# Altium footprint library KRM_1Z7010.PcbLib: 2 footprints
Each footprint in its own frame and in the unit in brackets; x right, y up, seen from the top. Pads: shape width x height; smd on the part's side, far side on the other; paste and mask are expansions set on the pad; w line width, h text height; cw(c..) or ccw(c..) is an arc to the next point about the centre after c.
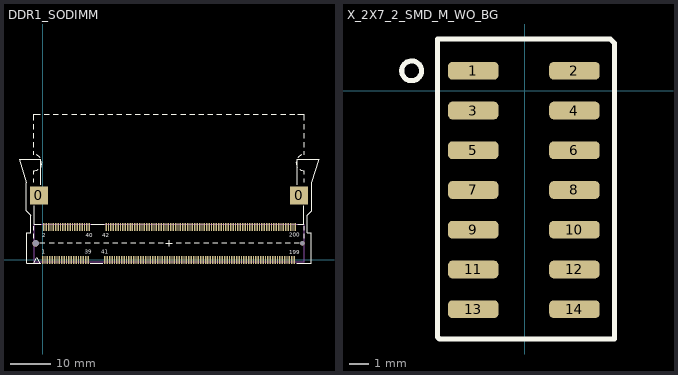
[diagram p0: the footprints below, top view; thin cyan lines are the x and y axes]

## DDR1_SODIMM [mm] "SO DIMM SOCKET DDR STD 2V5"
pads (204):
  round 1.55 hole 1.6 unplated: 0(-1.75,4.1)
  rect 4.5x4.6 smd: 0(-0.9,16.1) 0(64.2,16.1)
  round 1.05 hole 1.1 unplated: 0(65.05,4.1)
  rect 0.35x2 smd: 1(0,0) 2(0.3,8.2) 3(0.6,0) 4(0.9,8.2) 5(1.2,0) 6(1.5,8.2) 7(1.8,0) 8(2.1,8.2) 9(2.4,0) 10(2.7,8.2) 11(3,0) 12(3.3,8.2) 13(3.6,0) 14(3.9,8.2) 15(4.2,0) 16(4.5,8.2) 17(4.8,0) 18(5.1,8.2) 19(5.4,0) 20(5.7,8.2) 21(6,0) 22(6.3,8.2) 23(6.6,0) 24(6.9,8.2) 25(7.2,0) 26(7.5,8.2) 27(7.8,0) 28(8.1,8.2) 29(8.4,0) 30(8.7,8.2) 31(9,0) 32(9.3,8.2) 33(9.6,0) 34(9.9,8.2) 35(10.2,0) 36(10.5,8.2) 37(10.8,0) 38(11.1,8.2) 39(11.4,0) 40(11.7,8.2) 41(15.6,0) 42(15.9,8.2) 43(16.2,0) 44(16.5,8.2) 45(16.8,0) 46(17.1,8.2) 47(17.4,0) 48(17.7,8.2) 49(18,0) 50(18.3,8.2) 51(18.6,0) 52(18.9,8.2) 53(19.2,0) 54(19.5,8.2) 55(19.8,0) 56(20.1,8.2) 57(20.4,0) 58(20.7,8.2) 59(21,0) 60(21.3,8.2) 61(21.6,0) 62(21.9,8.2) 63(22.2,0) 64(22.5,8.2) 65(22.8,0) 66(23.1,8.2) 67(23.4,0) 68(23.7,8.2) 69(24,0) 70(24.3,8.2) 71(24.6,0) 72(24.9,8.2) 73(25.2,0) 74(25.5,8.2) 75(25.8,0) 76(26.1,8.2) 77(26.4,0) 78(26.7,8.2) 79(27,0) 80(27.3,8.2) 81(27.6,0) 82(27.9,8.2) 83(28.2,0) 84(28.5,8.2) 85(28.8,0) 86(29.1,8.2) 87(29.4,0) 88(29.7,8.2) 89(30,0) 90(30.3,8.2) 91(30.6,0) 92(30.9,8.2) 93(31.2,0) 94(31.5,8.2) 95(31.8,0) 96(32.1,8.2) 97(32.4,0) 98(32.7,8.2) 99(33,0) 100(33.3,8.2) 101(33.6,0) 102(33.9,8.2) 103(34.2,0) 104(34.5,8.2) 105(34.8,0) 106(35.1,8.2) 107(35.4,0) 108(35.7,8.2) 109(36,0) 110(36.3,8.2) 111(36.6,0) 112(36.9,8.2) 113(37.2,0) 114(37.5,8.2) 115(37.8,0) 116(38.1,8.2) 117(38.4,0) 118(38.7,8.2) 119(39,0) 120(39.3,8.2) 121(39.6,0) 122(39.9,8.2) 123(40.2,0) 124(40.5,8.2) 125(40.8,0) 126(41.1,8.2) 127(41.4,0) 128(41.7,8.2) 129(42,0) 130(42.3,8.2) 131(42.6,0) 132(42.9,8.2) 133(43.2,0) 134(43.5,8.2) 135(43.8,0) 136(44.1,8.2) 137(44.4,0) 138(44.7,8.2) 139(45,0) 140(45.3,8.2) 141(45.6,0) 142(45.9,8.2) 143(46.2,0) 144(46.5,8.2) 145(46.8,0) 146(47.1,8.2) 147(47.4,0) 148(47.7,8.2) 149(48,0) 150(48.3,8.2) 151(48.6,0) 152(48.9,8.2) 153(49.2,0) 154(49.5,8.2) 155(49.8,0) 156(50.1,8.2) 157(50.4,0) 158(50.7,8.2) 159(51,0) 160(51.3,8.2) 161(51.6,0) 162(51.9,8.2) 163(52.2,0) 164(52.5,8.2) 165(52.8,0) 166(53.1,8.2) 167(53.4,0) 168(53.7,8.2) 169(54,0) 170(54.3,8.2) 171(54.6,0) 172(54.9,8.2) 173(55.2,0) 174(55.5,8.2) 175(55.8,0) 176(56.1,8.2) 177(56.4,0) 178(56.7,8.2) 179(57,0) 180(57.3,8.2) 181(57.6,0) 182(57.9,8.2) 183(58.2,0) 184(58.5,8.2) 185(58.8,0) 186(59.1,8.2) 187(59.4,0) 188(59.7,8.2) 189(60,0) 190(60.3,8.2) 191(60.6,0) 192(60.9,8.2) 193(61.2,0) 194(61.5,8.2) 195(61.8,0) 196(62.1,8.2) 197(62.4,0) 198(62.7,8.2) 199(63,0) 200(63.3,8.2)
Top Overlay:
  lines w0.203: -2.15,-0.9 -1.45,0.525 -0.75,-0.9 ; -2.15,5.425 -2.15,6.55 ; -2.15,7.425 -2.15,8.425 ; -2.15,19.35 -2.15,20.325 ; -2.15,21.375 -2.15,22.3 ccw(c-2.15,24.3) -1.032,22.642 ; -2.15,26.3 -2.15,27.15 ; -2.15,28.175 -2.15,29.425 ; -2.15,30.45 -2.15,31.7 ; -2.15,32.725 -2.15,33.975 ; -2.15,34.978 -2.15,36.428 -0.6,36.428 ; -2.15,35 -2.15,36.25 ; -2.075,13.5 -2.075,8.925 -0.65,8.925 -0.4,8.925 ; -1.595,26.237 cw(c-2.15,24.3) -0.541,25.513 ; -0.65,4.3 0.6,4.3 ; -0.503,23.146 ccw(c-2.15,24.3) -0.146,24.475 ; -0.5,18.725 -0.5,25.1 -5.9,25.1 -4.1,19.325 -4.1,12.3 -2.9,11.1 -2.9,6.8 -3.9,6.8 -3.9,-0.9 -0.475,-0.9 ; 0.425,36.428 1.675,36.428 ; 1.625,4.3 2.875,4.3 ; 2.7,36.428 3.95,36.428 ; 3.9,4.3 5.15,4.3 ; 4.975,36.428 6.225,36.428 ; 6.175,4.3 7.425,4.3 ; 7.25,36.428 8.5,36.428 ; 8.45,4.3 9.7,4.3 ; 9.525,36.428 10.775,36.428 ; 10.725,4.3 11.975,4.3 ; 11.8,36.428 13.05,36.428 ; 11.925,-0.9 15.075,-0.9 ; 12.225,8.925 15.4,8.925 ; 13,4.3 14.25,4.3 ; 14.075,36.428 15.325,36.428 ; 15.275,4.3 16.525,4.3 ; 16.35,36.428 17.6,36.428 ; 17.55,4.3 18.8,4.3 ; 18.625,36.428 19.875,36.428 ; 19.825,4.3 21.075,4.3 ; 20.9,36.428 22.15,36.428 ; 22.1,4.3 23.35,4.3 ; 23.175,36.428 24.425,36.428 ; 24.375,4.3 25.625,4.3 ; 25.45,36.428 26.7,36.428 ; 26.65,4.3 27.9,4.3 ; 27.725,36.428 28.975,36.428 ; 28.925,4.3 30.175,4.3 ; 30,36.428 31.25,36.428 ; 30.825,4.1 32.475,4.1 ; 31.65,3.35 31.65,4.825 ; 32.275,36.428 33.525,36.428 ; 33.475,4.3 34.725,4.3 ; 34.55,36.428 35.8,36.428 ; 35.75,4.3 37,4.3 ; 36.825,36.428 38.075,36.428 ; 38.025,4.3 39.275,4.3 ; 39.1,36.428 40.35,36.428 ; 40.3,4.3 41.55,4.3 ; 41.375,36.428 42.625,36.428 ; 42.575,4.3 43.825,4.3 ; 43.65,36.428 44.9,36.428 ; 44.85,4.3 46.1,4.3 ; 45.925,36.428 47.175,36.428 ; 47.125,4.3 48.375,4.3 ; 48.2,36.428 49.45,36.428 ; 49.4,4.3 50.65,4.3 ; 50.475,36.428 51.725,36.428 ; 51.675,4.3 52.925,4.3 ; 52.75,36.428 54,36.428 ; 53.95,4.3 55.2,4.3 ; 55.025,36.428 56.275,36.428 ; 56.225,4.3 57.475,4.3 ; 57.3,36.428 58.55,36.428 ; 58.5,4.3 59.75,4.3 ; 59.575,36.428 60.825,36.428 ; 60.775,4.3 62.025,4.3 ; 61.85,36.428 63.1,36.428 ; 63.05,4.3 64.3,4.3 ; 63.446,24.475 ccw(c65.45,24.3) 63.803,23.146 ; 63.575,-0.9 67.2,-0.9 67.2,6.8 66.2,6.8 66.2,11.1 67.4,12.3 67.4,19.325 69.2,25.1 63.8,25.1 63.8,18.725 ; 63.841,25.513 cw(c65.45,24.3) 64.895,26.237 ; 63.85,8.925 65.375,8.925 65.375,13.5 ; 63.9,36.428 65.45,36.428 ; 64.125,36.428 65.45,36.428 ; 64.332,22.642 ccw(c65.45,24.3) 65.45,22.3 65.45,21.375 ; 65.45,5.425 65.45,6.55 ; 65.45,7.425 65.45,8.425 ; 65.45,19.35 65.45,20.325 ; 65.45,26.3 65.45,27.15 ; 65.45,28.175 65.45,29.425 ; 65.45,30.45 65.45,31.7 ; 65.45,32.725 65.45,33.975 ; 65.45,34.978 65.45,36.428 ; 65.45,35 65.45,36.25
  text "39" at 10.575,1.5 h1.02
  text "41" at 14.65,1.5 h1.02
  text "199" at 61.75,1.425 h1.02
  text "200" at 61.75,5.7 h1.02
  text "1" at -0.25,1.525 h1.02
  text "40" at 10.85,5.6 h1.02
  text "2" at -0.075,5.675 h1.02
  text "42" at 15,5.65 h1.02
Mechanical 1:
  lines w0.1: -2.032,-0.508 -2.032,8.89 65.532,8.89 65.532,-0.508 -2.032,-0.508
3D body "c-1473005-1-j1-3d.stp": height 5.2, standoff -0.7, extent -4.1,-0.925 67.4,25.125

## X_2X7_2_SMD_M_WO_BG [mm] "XILINX JTAG HEADER"
height 3.5
pads (14):
  rrect50% 2.54x0.89 smd: 1(-2.6,1) 2(2.495,1) 3(-2.6,-1) 4(2.495,-1) 5(-2.6,-3) 6(2.495,-3) 7(-2.6,-5) 8(2.495,-5) 9(-2.6,-7) 10(2.495,-7) 11(-2.6,-9) 12(2.495,-9) 13(-2.6,-11) 14(2.495,-11)
Top Overlay:
  circle w0.254: c-5.7,1 r0.5
  lines w0.254: -4.4,-12.4 -4.4,2.6 4.3,2.6 4.5,2.4 4.5,-12.5 -4.3,-12.5 -4.4,-12.4
3D body "878321420_xilinx_prog_header.stp": height 7.6, standoff -1, extent -3.15,-13.3 3.15,3.35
